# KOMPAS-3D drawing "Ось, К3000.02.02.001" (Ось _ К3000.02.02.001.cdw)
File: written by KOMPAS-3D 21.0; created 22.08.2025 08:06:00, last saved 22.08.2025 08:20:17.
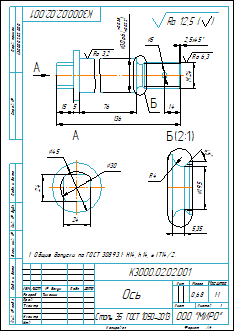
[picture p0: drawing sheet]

Sheet 1: A4, portrait

Document properties: Автор: Lutik; Полное имя файла: C:\Users\Lutik\YandexDisk\Документы\Новая папка\Бабка задняя\2D\Опора роликовая_К3000.02.02.000\Ось _ К3000.02.02.001.cdw; Знак неуказанной шероховатости: 4; Параметр неуказанной шероховатости: Ra 12,5; Масса: 0.680029

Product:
- Part/product: Ось  | designation К3000.02.02.001
    Материал: Сталь 35  ГОСТ 1050-2013 (density 7826 kg/m3)
    Масса: 0.680029

Title block, sheet 1: Наименование: Ось; designation: К3000.02.02.001; Материал: Сталь 35  ГОСТ 1050-2013; Масса: 0,68; Количество листов документа: 1; organisation: ООО "МИРО"; Форматы листов документа: A4; Разработал: Тимонин

Views: Вид 1, Сверху, Вид по стрелке 2, Выносной элемент 3, Вид по стрелке А, Выносной элемент Б, Выносной элемент
Referenced files in C:\Users\Lutik\YandexDisk\Документы\Новая папка\Бабка задняя\3D\: Ось.m3d
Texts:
  Ra 3,2
  Ra 6,3
  Ra 12,5
  Ra 12,5 ( )
  К3000.02.02.001 Ось
Dimensions and other numbers on the sheet: 30; 136; 15; 5; 76; 14; 24; 2,5; 8; 45; 19,5; 5,35; 4; 1:1; 1; 0,68

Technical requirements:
  Общие допуски по ГОСТ 30893.1: Н14, h14, ± IT14/2.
